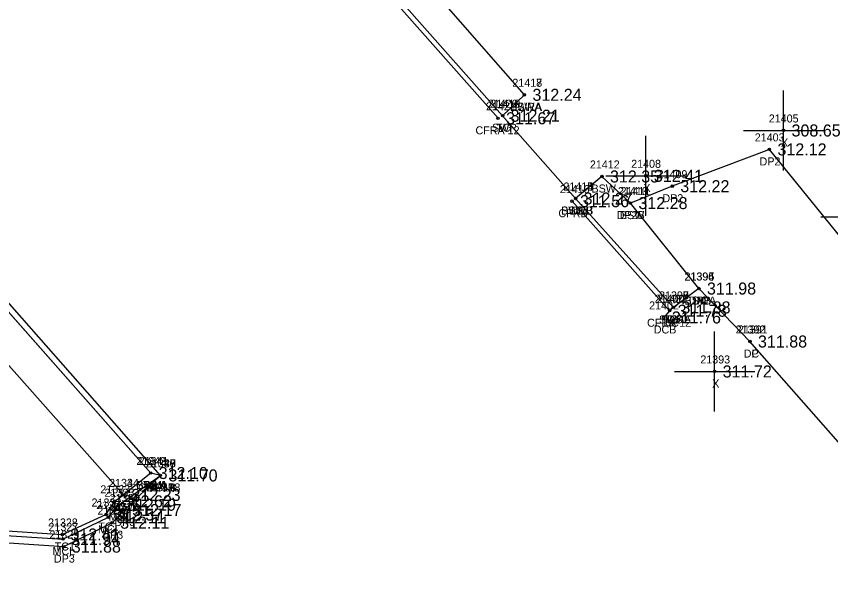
# Model space of a CAD drawing. Extents: x 1970242 to 1971082, y 803104 to 803947.
# Drawn here: x 1970327.3 to 1970429, y 803802.3 to 803871.8 of the extents above; entities that cross this region are included whole.
import ezdxf

# ---------------------------------------------------------------- set-up
doc = ezdxf.new("R2010")
doc.units = 0
for name, color, linetype in [('RD_DTM_BkLn2', 7, 'Continuous'), ('RD_EX_Conc', 7, 'Continuous'), ('RD_EX_Conc_txCode', 7, 'Continuous'), ('RD_EX_Driveway', 7, 'Continuous'), ('RD_EX_Driveway_txCode', 7, 'Continuous'), ('RD_EX_Misc', 7, 'Continuous'), ('RD_EX_Misc_txCode', 7, 'Continuous'), ('RD_EX_TX_Conc_ELEV', 7, 'Continuous'), ('RD_EX_TX_Driveway_ELEV', 7, 'Continuous'), ('RD_EX_TX_Misc_ELEV', 7, 'Continuous'), ('RD_SMD_Locator', 7, 'Continuous')]:
    doc.layers.add(name, color=color, linetype=linetype)

msp = doc.modelspace()

# ---------------------------------------------------------------- linework, layer by layer
at = {"layer": 'RD_DTM_BkLn2'}
for points in [[(1970409.39, 803835.52), (1970397.17, 803849.11), (1970388.06, 803859.44), (1970351.13, 803901.09)], [(1970345.34, 803814.56), (1970344.12, 803814.86), (1970297.89, 803867.18)], [(1970260.68, 803806.01), (1970271.72, 803808.94), (1970291.19, 803809.98), (1970333.09, 803807.19), (1970338.54, 803809.68), (1970339.63, 803811.33), (1970340.72, 803812.13)]]:
    msp.add_lwpolyline(points, dxfattribs=at)
at = {"layer": 'RD_EX_Conc'}
for p, q in [((1970390.79, 803862.05), (1970354.1, 803903.96)), ((1970344.12, 803814.86), (1970297.89, 803867.18)), ((1970345.34, 803814.56), (1970298.49, 803867.71)), ((1970409.39, 803835.52), (1970397.17, 803849.11)), ((1970408.92, 803835.11), (1970396.73, 803848.78))]:
    msp.add_line(p, q, dxfattribs=at)
for points in [[(1970390.79, 803862.05), (1970388.06, 803859.44), (1970351.13, 803901.09), (1970354.1, 803903.96)], [(1970387.5, 803859.12), (1970350.67, 803900.7), (1970351.13, 803901.09)], [(1970344.12, 803814.86), (1970340.72, 803812.13), (1970294.54, 803864.17)], [(1970412.58, 803837.88), (1970404.02, 803848.54), (1970400.47, 803851.86), (1970397.17, 803849.11)], [(1970435.37, 803803.84), (1970435.97, 803804.43), (1970436.33, 803804.84), (1970439.8, 803807.61), (1970418.95, 803831.27), (1970412.58, 803837.88), (1970409.39, 803835.52), (1970408.92, 803835.11), (1970408.19, 803834.27)], [(1970260.96, 803805.21), (1970271.85, 803808.4), (1970291.28, 803809.29), (1970333.16, 803806.62), (1970338.84, 803809.35), (1970340.15, 803810.9), (1970345.34, 803814.56)]]:
    msp.add_lwpolyline(points, dxfattribs=at)
at = {"layer": 'RD_EX_Driveway'}
for points in [[(1970497.05, 803769.77), (1970471.73, 803797.23), (1970462.7, 803807.92), (1970453.08, 803818.73), (1970431.42, 803842.89), (1970421.38, 803855.24), (1970409.25, 803850.65), (1970404.02, 803848.54)], [(1970484.2, 803757.17), (1970475.49, 803767.3), (1970449.05, 803797.2), (1970439.8, 803807.61), (1970418.95, 803831.27), (1970412.58, 803837.88)], [(1970261.71, 803804.6), (1970272.07, 803807.38), (1970291.31, 803808.49), (1970333.27, 803805.68), (1970339.31, 803808.66), (1970340.83, 803810.24), (1970345.34, 803814.56)]]:
    msp.add_lwpolyline(points, dxfattribs=at)
at = {"layer": 'RD_EX_Misc'}
for p, q in [((1970423.14, 803852.6), (1970423.14, 803862.6)), ((1970418.14, 803857.6), (1970428.14, 803857.6)), ((1970405.95, 803846.94), (1970405.95, 803856.94)), ((1970400.95, 803851.94), (1970410.95, 803851.94)), ((1970427.78, 803846.83), (1970437.78, 803846.83)), ((1970414.54, 803822.53), (1970414.54, 803832.53)), ((1970409.54, 803827.53), (1970419.54, 803827.53))]:
    msp.add_line(p, q, dxfattribs=at)
at = {"layer": 'RD_SMD_Locator'}
for centre in [(1970390.79, 803862.05), (1970390.79, 803862.05), (1970387.5, 803859.12), (1970388.06, 803859.44), (1970388.06, 803859.44), (1970423.14, 803857.6), (1970421.38, 803855.24), (1970400.47, 803851.86), (1970405.95, 803851.94), (1970409.25, 803850.65), (1970396.73, 803848.78), (1970397.17, 803849.11), (1970397.17, 803849.11), (1970397.17, 803849.11), (1970404.02, 803848.54), (1970404.02, 803848.54), (1970412.58, 803837.88), (1970412.58, 803837.88), (1970412.58, 803837.88), (1970409.39, 803835.52), (1970409.39, 803835.52), (1970409.39, 803835.52), (1970408.92, 803835.11), (1970408.92, 803835.11), (1970408.19, 803834.27), (1970418.95, 803831.27), (1970418.95, 803831.27), (1970414.54, 803827.53), (1970344.12, 803814.86), (1970344.12, 803814.86), (1970344.12, 803814.86), (1970345.34, 803814.56), (1970345.34, 803814.56), (1970345.34, 803814.56), (1970345.34, 803814.56), (1970340.72, 803812.13), (1970340.72, 803812.13), (1970339.63, 803811.33), (1970340.15, 803810.9), (1970340.83, 803810.24), (1970338.54, 803809.68), (1970338.84, 803809.35), (1970339.31, 803808.66), (1970333.09, 803807.19), (1970333.16, 803806.62), (1970333.27, 803805.68)]:
    msp.add_circle(centre, 0.15, dxfattribs=at)

# ---------------------------------------------------------------- texts
at = {"layer": 'RD_EX_Conc_txCode'}
for s, p in [('21417', (1970389.28, 803863.05)), ('21418', (1970389.28, 803863.05)), ('21421', (1970385.99, 803860.12)), ('21420', (1970386.22, 803860.44)), ('21419', (1970386.55, 803860.44)), ('SWRA', (1970388.99, 803860.05)), ('BSWA', (1970388.99, 803860.05)), ('CFRA 12', (1970384.68, 803857.12)), ('SWR', (1970386.74, 803857.44)), ('TC', (1970387.26, 803857.44)), ('21412', (1970398.96, 803852.86)), ('21413', (1970395.66, 803850.11)), ('21414', (1970395.66, 803850.11)), ('21415', (1970395.66, 803850.11)), ('21416', (1970395.2, 803849.78)), ('BSW', (1970399.16, 803849.86)), ('21411', (1970402.79, 803849.54)), ('SWRB', (1970395.38, 803847.11)), ('BSWB', (1970395.38, 803847.11)), ('TC', (1970396.38, 803847.11)), ('CFRB', (1970395.03, 803846.78)), ('BSW', (1970402.7, 803846.54)), ('21396', (1970410.76, 803838.88)), ('21394', (1970410.79, 803838.88)), ('21400', (1970407.05, 803836.11)), ('21401', (1970407.37, 803836.11)), ('21397', (1970407.6, 803836.52)), ('21398', (1970407.6, 803836.52)), ('21399', (1970407.6, 803836.52)), ('BSWA', (1970410.78, 803835.88)), ('DC', (1970411.8, 803835.88)), ('21402', (1970406.36, 803835.27)), ('CFRA 12', (1970406.1, 803833.11)), ('SWRA', (1970407.59, 803833.52)), ('TCA', (1970408.11, 803833.52)), ('DC', (1970408.14, 803833.11)), ('DC', (1970408.61, 803833.52)), ('DCB', (1970406.94, 803832.27)), ('21391', (1970417.44, 803832.27)), ('DC', (1970418.17, 803829.27)), ('21342', (1970342.33, 803815.86)), ('21343', (1970342.33, 803815.86)), ('21341', (1970342.61, 803815.86)), ('21340', (1970343.51, 803815.56)), ('21337', (1970343.55, 803815.56)), ('21339', (1970343.55, 803815.56)), ('21333', (1970337.83, 803812.33)), ('21334', (1970338.93, 803813.13)), ('21344', (1970338.93, 803813.13)), ('SWLA', (1970342.34, 803812.86)), ('BSWA', (1970342.32, 803812.86)), ('CFLA 18', (1970342.55, 803812.56)), ('TC1', (1970343.16, 803812.86)), ('MCLB', (1970343.58, 803812.56)), ('TC1A', (1970343.89, 803812.56)), ('21335', (1970338.35, 803811.9)), ('21332', (1970336.74, 803810.68)), ('21331', (1970337.32, 803810.35)), ('TC1', (1970338.66, 803809.33)), ('TC1B', (1970339.29, 803810.13)), ('BSW', (1970339.41, 803810.13)), ('MCL', (1970338.86, 803808.9)), ('21328', (1970331.3, 803808.19)), ('21327', (1970331.36, 803807.62)), ('TC1', (1970337.58, 803807.68)), ('MCL', (1970337.54, 803807.35)), ('TC1', (1970332.13, 803805.19)), ('MCL', (1970331.87, 803804.62))]:
    msp.add_text(s, height=1, dxfattribs=at).set_placement(p)
at = {"layer": 'RD_EX_Driveway_txCode'}
for s, p in [('21403', (1970419.55, 803856.24)), ('DP2', (1970420.15, 803853.24)), ('21409', (1970407.42, 803851.65)), ('21410', (1970402.47, 803849.54)), ('DP2', (1970408.02, 803848.65)), ('DP2B', (1970402.32, 803846.54)), ('21395', (1970410.79, 803838.88)), ('DPB', (1970411.33, 803835.88)), ('21392', (1970417.16, 803832.27)), ('DP', (1970418.17, 803829.27)), ('21338', (1970343.55, 803815.56)), ('DP3B', (1970343.64, 803812.56)), ('21336', (1970339.01, 803811.24)), ('21330', (1970337.47, 803809.66)), ('DP3', (1970339.6, 803808.24)), ('21329', (1970331.48, 803806.68)), ('DP3', (1970338.08, 803806.66)), ('DP3', (1970332.04, 803803.68))]:
    msp.add_text(s, height=1, dxfattribs=at).set_placement(p)
at = {"layer": 'RD_EX_Misc_txCode'}
for s, p in [('21405', (1970421.3, 803858.6)), ('X', (1970422.82, 803855.6)), ('21408', (1970404.12, 803852.94)), ('X', (1970405.64, 803849.94)), ('21393', (1970412.75, 803828.53)), ('X', (1970414.23, 803825.53))]:
    msp.add_text(s, height=1, dxfattribs=at).set_placement(p)
at = {"layer": 'RD_EX_TX_Conc_ELEV'}
for s, p in [('312.24', (1970391.79, 803861.3)), ('312.24', (1970391.79, 803861.3)), ('312.21', (1970389.06, 803858.69)), ('312.21', (1970389.06, 803858.69)), ('311.67', (1970388.5, 803858.37)), ('312.35', (1970401.47, 803851.11)), ('311.56', (1970397.73, 803848.03)), ('312.27', (1970398.17, 803848.36)), ('312.27', (1970398.17, 803848.36)), ('312.27', (1970398.17, 803848.36)), ('312.28', (1970405.02, 803847.79)), ('311.98', (1970413.58, 803837.13)), ('311.98', (1970413.58, 803837.13)), ('311.73', (1970409.92, 803834.36)), ('311.73', (1970409.92, 803834.36)), ('311.88', (1970410.39, 803834.77)), ('311.88', (1970410.39, 803834.77)), ('311.88', (1970410.39, 803834.77)), ('311.76', (1970409.19, 803833.52)), ('311.88', (1970419.95, 803830.52)), ('312.10', (1970345.12, 803814.11)), ('312.10', (1970345.12, 803814.11)), ('312.10', (1970345.12, 803814.11)), ('311.70', (1970346.34, 803813.81)), ('311.70', (1970346.34, 803813.81)), ('311.70', (1970346.34, 803813.81)), ('312.23', (1970341.72, 803811.38)), ('312.23', (1970341.72, 803811.38)), ('312.62', (1970340.63, 803810.58)), ('312.19', (1970341.15, 803810.15)), ('312.57', (1970339.54, 803808.93)), ('312.11', (1970339.84, 803808.6)), ('312.41', (1970334.09, 803806.44)), ('311.94', (1970334.16, 803805.87))]:
    msp.add_text(s, height=1.5, dxfattribs=at).set_placement(p)
at = {"layer": 'RD_EX_TX_Driveway_ELEV'}
for s, p in [('312.12', (1970422.38, 803854.49)), ('312.22', (1970410.25, 803849.9)), ('312.28', (1970405.02, 803847.79)), ('311.98', (1970413.58, 803837.13)), ('311.88', (1970419.95, 803830.52)), ('311.70', (1970346.34, 803813.81)), ('312.17', (1970341.83, 803809.49)), ('312.11', (1970340.31, 803807.91)), ('311.88', (1970334.27, 803804.93))]:
    msp.add_text(s, height=1.5, dxfattribs=at).set_placement(p)
at = {"layer": 'RD_EX_TX_Misc_ELEV'}
for s, p in [('308.65', (1970424.14, 803856.85)), ('312.41', (1970406.95, 803851.19)), ('311.72', (1970415.54, 803826.78))]:
    msp.add_text(s, height=1.5, dxfattribs=at).set_placement(p)

doc.saveas('drawing.dxf')
